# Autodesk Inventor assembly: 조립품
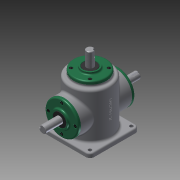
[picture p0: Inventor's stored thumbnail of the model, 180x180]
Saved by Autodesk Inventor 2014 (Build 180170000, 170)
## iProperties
Created: 2015-10
Part Number: 조립품
Document SubType Name: Assembly
Designer: 시험용
Author: 시험용
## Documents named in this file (14)
- D:\451008V1027\조립품.iam
- D:\451008V1027\M4.ipt
- D:\451008V1027\메인 베벨기어.ipt
- D:\451008V1027\메인 축.ipt
- 메인 축.ipt
- D:\451008V1027\베어링 6203.ipt
- D:\451008V1027\본체.ipt
- D:\451008V1027\서브 베벨기어.ipt
- D:\451008V1027\서브 축.ipt
- 서브 축.ipt
- D:\451008V1027\오일실.ipt
- D:\451008V1027\커버.ipt
- D:\451008V1027\키 4x4.ipt
- D:\451008V1027\키 5x5.ipt
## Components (12 placed, 1 different names)
1. M4:1
2. M4:2
3. M4:3
4. M4:4
5. M4:6
6. M4:7
7. M4:8
8. M4:9
9. M4:5
10. M4:10
11. M4:11
12. M4:12
